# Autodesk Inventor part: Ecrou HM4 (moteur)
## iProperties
Library Location: C:\Program Files\Autodesk\Inventor 6\content
Library: local
SubLibrary: ISO
Family: 51
Member: 60
Member Major Revision: 1
Member Minor Revision: 1
Comments: To add or edit properties for Autodesk Inventor files, use iProperties.
Created: 2005-01
Part Number: Ecrou HM4 (moteur)
Vendor: Autodesk Inc.
Document SubType Name: Modeling
Designer: lolo (Laurent Moretti)
Description: Ecrou hexagonal
Standard: ISO 4032 M4
Alert: To add or edit properties for Autodesk Inventor files, use iProperties.
Control State: 0
Master: False
Checked Out: False
Shininess: 64.0
Length Units: 11269
Angle Units: 11279
Time Units: 11290
Mass Units: 11283
Length Display Precision: 3
Angle Display Precision: 2
Compacted: True
EGR: 1
Density: 0.0
Volumn: 0.0
Area: 0.0
PropertySet Name: Model Information
Author: lolo (Laurent Moretti)
Revision Number: 1
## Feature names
1. Corps [Extrusion]
2. Chanfrein1 [Revolution]
3. Filetage [Hole]
4. Chanfrein2 [Chamfer]
5. Chanfrein3 [Chamfer]
